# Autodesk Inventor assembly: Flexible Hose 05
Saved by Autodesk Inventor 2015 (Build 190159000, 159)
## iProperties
Created: 2013-02
Part Number: Flexible Hose 05
Document SubType Name: Assembly
Designer: Marci
Name: Hydraulic Hose - No Fittings
ActiveState: True
PipeType: Flexible Hose
Material: UnInitValue
Standard: UnInitValue
FittingMaterial: UnInitValue
FittingStandard: UnInitValue
RouteDirection90: UnInitValue
RouteDirection45: UnInitValue
IsFlanged: UnInitValue
IsButtWelded: UnInitValue
DiameterType: Nominal
Diameter: 1/4
Schedule: ID=0.25
OD: 1,4986
ID: 0,635
Ending: UnInitValue
IntermediateSegmentsMin: UnInitValue
IntermediateSegmentsMax: UnInitValue
IntermediateSegmentsInc: UnInitValue
TerminationSegmentsMin: UnInitValue
TerminationSegmentsMax: UnInitValue
TerminationSegmentsInc: UnInitValue
RoundUpValue: 0.125 in
DefaultBendRadius: UnInitValue
BendRadius: 0.500 in
PipingComponentColor: Blue (Flat)
PipeKey: v3#d489867e-ac9b-47ea-b952-0a1b885f66be#1
CouplingKey: UnInitValue
Elbow90Key: UnInitValue
Elbow45Key: UnInitValue
SuppressStartFitting: True
SuppressEndFitting: True
FlangeKey: UnInitValue
GasketKey: UnInitValue
Gap: UnInitValue
UseSubASM: True
_ComponentInfo: <CS><C N="Pipe" R="0,749300" OR="0,749300" IR="0,317500" PL="PL" PartType="pipe" SymKey="" PN="Parker hidraulikatömlő - No Skive 1/4"><CO N="1"><FE V="0"/><FD V
ShowGap: UnInitValue
MixedUnits: UnInitValue
UseFlangsForCouplings: UnInitValue
IsSelfDraining: UnInitValue
ElbowCustomKey: UnInitValue
Angle: UnInitValue
Author: Marci
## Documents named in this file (3)
- C:\Users\Andrew Almeida\Documents\Projeto WS2015\WS2015 CAD Data ANLAS\01\Pneumatic System\Engine\Pneumatikus hajtás\Teljes hajtás\AIP\Tube and Pipe\Run06\Teljes hajtás.Hose05.iam
- C:\Users\Andrew Almeida\Documents\Projeto WS2015\WS2015 CAD Data ANLAS\01\Pneumatic System\Engine\Pneumatikus hajtás\Teljes hajtás\AIP\Tube and Pipe\Run06\Teljes hajtás.Hose05.ipt
- C:\Users\Andrew Almeida\Documents\Projeto WS2015\WS2015 CAD Data ANLAS\01\Pneumatic System\Engine\Pneumatikus hajtás\Teljes hajtás\AIP\Tube and Pipe\Run06\pifhose.1360342873062.ipt
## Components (2 placed, 2 different names)
1. Hose05
2. Flexible Hose:1
